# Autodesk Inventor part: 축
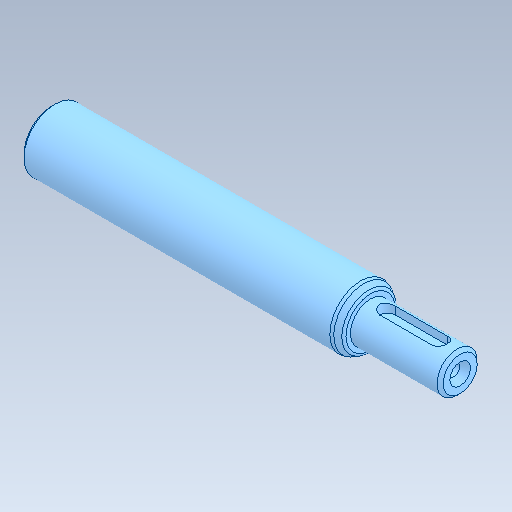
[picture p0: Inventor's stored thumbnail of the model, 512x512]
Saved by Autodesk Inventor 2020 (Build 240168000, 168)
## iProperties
Created: 2024-09
Part Number: 축
Material: 강철, 탄소
Document SubType Name: Modeling
Designer: oem
Density: 7.85 g/cm^3
Appearance: 기본값
Author: jhkim
Sending System: Autodesk Inventor 2025
Preprocessor: ST-DEVELOPER v20
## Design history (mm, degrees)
feature "솔리드1"
node "솔리드2"
